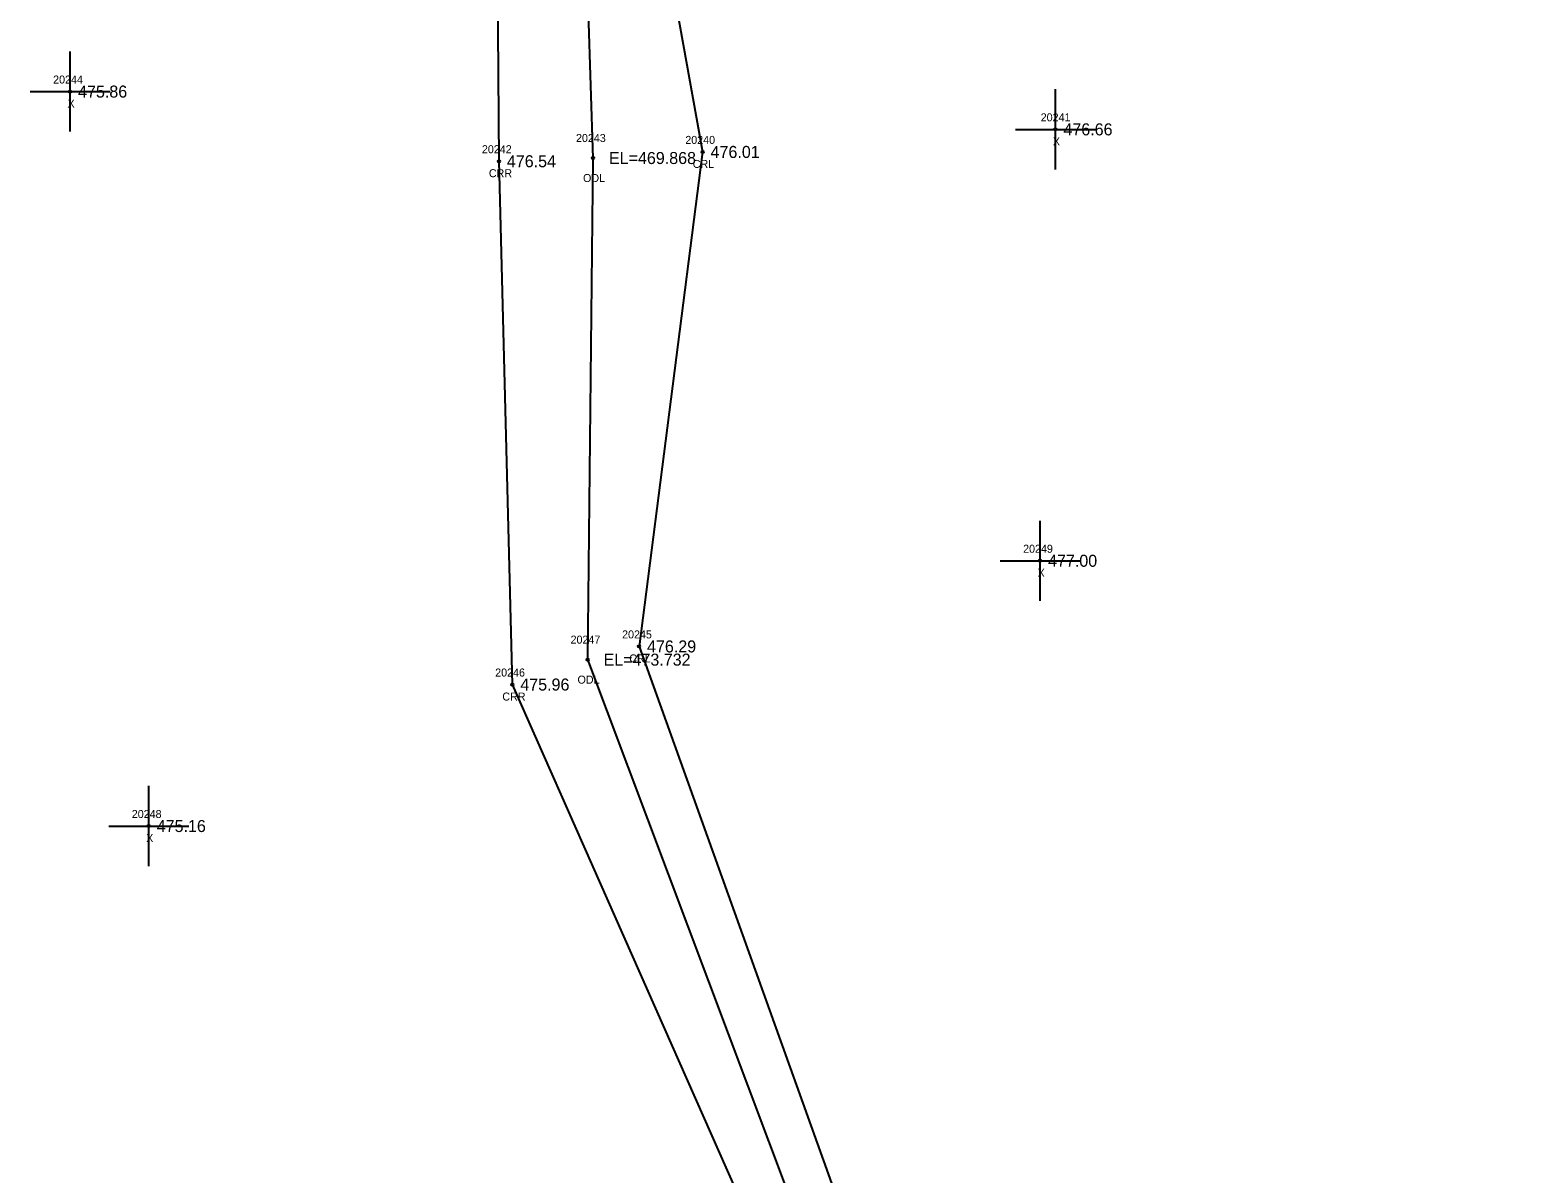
# Model space of a CAD drawing. Extents: x 1789565 to 1790548, y 909019 to 910194.
# Drawn here: x 1789853 to 1790040.8, y 909888.9 to 910031.8 of the extents above; entities that cross this region are included whole.
import ezdxf

# ---------------------------------------------------------------- set-up
doc = ezdxf.new("R2010")
doc.units = 0
for name, color, linetype in [('RD_EX_H2O', 7, 'Continuous'), ('RD_EX_H2O_txCode', 7, 'Continuous'), ('RD_EX_Misc', 7, 'Continuous'), ('RD_EX_Misc_txCode', 7, 'Continuous'), ('RD_EX_TX_H2O_ELEV', 7, 'Continuous'), ('RD_EX_TX_Misc_ELEV', 7, 'Continuous'), ('RD_SMD_Locator', 7, 'Continuous')]:
    doc.layers.add(name, color=color, linetype=linetype)

msp = doc.modelspace()

# ---------------------------------------------------------------- linework, layer by layer
at = {"layer": 'RD_EX_H2O'}
for points in [[(1789916.44, 910152.62), (1789911.22, 910059.17), (1789911.57, 910015.4), (1789913.25, 909950.04), (1789954.03, 909857.92), (1789966.14, 909807.85), (1790000.75, 909734.57), (1790025.55, 909650.06), (1790037.59, 909635.91)], [(1789926.75, 910151.78), (1789921.87, 910061.22), (1789923.33, 910015.8), (1789922.65, 909953.15), (1789957.79, 909859.65), (1789976.3, 909811.78), (1790009.05, 909737.59), (1790033.3, 909656.58), (1790043.84, 909640.77), (1790040.94, 909620.44), (1790068.41, 909598.88), (1790105.46, 909552.21), (1790128.28, 909493.4), (1790125.72, 909445.59), (1790167.31, 909436.17), (1790202.14, 909447.88), (1790216.41, 909437.36), (1790196.97, 909382.86), (1790209.47, 909371.8), (1790248.65, 909379.51), (1790333.47, 909404.65), (1790412.72, 909370.84), (1790438.82, 909377.48), (1790480.23, 909327.32)], [(1789942.19, 910149.47), (1789928.94, 910061.47), (1789937.03, 910016.56), (1789929.09, 909954.8), (1789962.46, 909861.74), (1789984.97, 909814.65), (1790017.82, 909740.15), (1790045.4, 909660.05), (1790055.69, 909646.96), (1790055.38, 909644.82), (1790053.69, 909634.91), (1790054.91, 909627.64), (1790075.55, 909607.72), (1790122.18, 909568.31), (1790142.55, 909490.86), (1790145.56, 909467.27), (1790204.21, 909464.64), (1790228.21, 909444.34), (1790208.83, 909385.44), (1790245.53, 909398.45), (1790340.56, 909420.98), (1790422.56, 909390.06), (1790444.95, 909390.88), (1790496, 909329.5)]]:
    msp.add_lwpolyline(points, dxfattribs=at)
at = {"layer": 'RD_EX_Misc'}
for p, q in [((1789857.98, 910019.1), (1789857.98, 910029.1)), ((1789852.98, 910024.1), (1789862.98, 910024.1)), ((1789981.13, 910014.38), (1789981.13, 910024.38)), ((1789976.13, 910019.38), (1789986.13, 910019.38)), ((1789979.21, 909960.5), (1789979.21, 909970.5)), ((1789974.21, 909965.5), (1789984.21, 909965.5)), ((1789867.81, 909927.37), (1789867.81, 909937.37)), ((1789862.81, 909932.37), (1789872.81, 909932.37))]:
    msp.add_line(p, q, dxfattribs=at)
at = {"layer": 'RD_SMD_Locator'}
for centre in [(1789857.98, 910024.1), (1789981.13, 910019.38), (1789923.33, 910015.8), (1789937.03, 910016.56), (1789911.57, 910015.4), (1789979.21, 909965.5), (1789929.09, 909954.8), (1789922.65, 909953.15), (1789913.25, 909950.04), (1789867.81, 909932.37)]:
    msp.add_circle(centre, 0.15, dxfattribs=at)

# ---------------------------------------------------------------- texts
at = {"layer": 'RD_EX_H2O_txCode'}
for s, p in [('20243', (1789921.21, 910017.8)), ('20240', (1789934.87, 910017.56)), ('20242', (1789909.45, 910016.4)), ('CRR', (1789910.32, 910013.4)), ('ODL', (1789922.09, 910012.8)), ('CRL', (1789935.8, 910014.56)), ('20247', (1789920.53, 909955.15)), ('20245', (1789926.97, 909955.8)), ('CRL', (1789927.86, 909952.8)), ('20246', (1789911.11, 909951.04)), ('ODL', (1789921.4, 909950.15)), ('CRR', (1789912, 909948.04))]:
    msp.add_text(s, height=1, dxfattribs=at).set_placement(p)
at = {"layer": 'RD_EX_Misc_txCode'}
for s, p in [('20244', (1789855.86, 910025.1)), ('X', (1789857.66, 910022.1)), ('20241', (1789979.29, 910020.38)), ('X', (1789980.81, 910017.38)), ('20249', (1789977.09, 909966.5)), ('X', (1789978.9, 909963.5)), ('20248', (1789865.69, 909933.37)), ('X', (1789867.49, 909930.37))]:
    msp.add_text(s, height=1, dxfattribs=at).set_placement(p)
at = {"layer": 'RD_EX_TX_H2O_ELEV'}
for s, p in [('476.54', (1789912.57, 910014.65)), ('EL=469.868', (1789925.33, 910015.05)), ('476.01', (1789938.03, 910015.81)), ('476.29', (1789930.09, 909954.05)), ('EL=473.732', (1789924.65, 909952.4)), ('475.96', (1789914.25, 909949.29))]:
    msp.add_text(s, height=1.5, dxfattribs=at).set_placement(p)
at = {"layer": 'RD_EX_TX_Misc_ELEV'}
for s, p in [('475.86', (1789858.98, 910023.35)), ('476.66', (1789982.13, 910018.63)), ('477.00', (1789980.21, 909964.75)), ('475.16', (1789868.81, 909931.62))]:
    msp.add_text(s, height=1.5, dxfattribs=at).set_placement(p)

doc.saveas('drawing.dxf')
